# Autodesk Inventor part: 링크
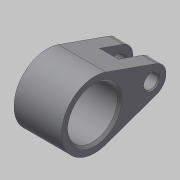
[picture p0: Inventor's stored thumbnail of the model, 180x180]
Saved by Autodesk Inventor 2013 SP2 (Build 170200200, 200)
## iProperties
Created: 2016-08
Part Number: 링크
Material: 강철, 탄소
Document SubType Name: Modeling
Designer: mduedu
Density: 7.87 g/cm^3
Author: mduedu
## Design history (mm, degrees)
sketch "스케치1"
  geometry: L1 (26, 5.657)-(4.667, 13.199); L2 (26, -5.657)-(4.667, -13.199); C1 r 10.5 at (0, 0); C2 r 3 at (24, 0); A1 r 14 centre (0, 0) between (4.667, 13.199) and (4.667, -13.199); A2 r 6 centre (24, 0) between (26, 5.657) and (26, -5.657); 1 further point
  constraints: 4 centre point, 4 end point, 4 point on circle, 4 tangent, 3 coincident, 1 horizontal alignment
  dimensions: "d0" = 28 diameter of A1; "d2" = 12 diameter of A2; "d3" = 24 distance of A2.centre point (0, 0); "d4" = 21 diameter of C1; "d5" = 6 diameter of C2
extrude "돌출1" new body sketch "스케치1" stored distance "d6" = 20; taper "d7" = 0 deg
sketch "스케치2"
  geometry: L1 (-10, 30)-(10, 30) reference; L2 (0, 0)-(0, 30); L3 (-4, 30)-(4, 30); L4 (4, 30)-(4, 16); L5 (4, 16)-(-4, 16); L6 (-4, 16)-(-4, 30)
  constraints: 10 end point, 2 midpoint, 2 parallel, 1 horizontal, 1 perpendicular, 1 point on line
  dimensions: "d8" = 8 distance between parallel lines of L4 L6; "d10" = 14 distance of L3.end L4.end
extrude "돌출2" cut sketch "스케치2" stored distance "d11" = 20; taper "d12" = 0 deg
chamfer "모따기1" distance "d13" = 1; stored, may be unused: second distance "d14" = 2, angle "d15" = 45 deg
chamfer "모따기2" distance "d16" = 0.5; stored, may be unused: second distance "d17" = 2, angle "d18" = 45 deg
node "솔리드1"
